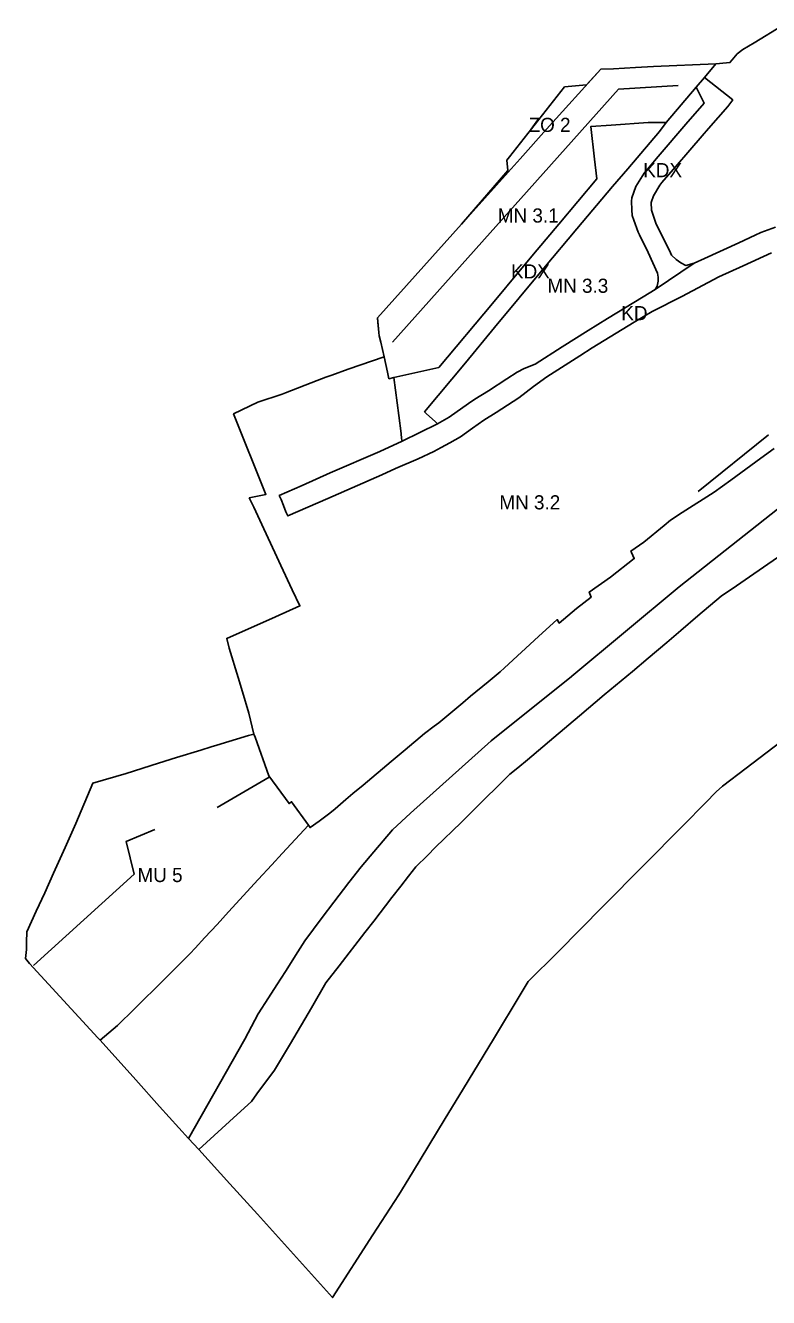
# Model space of a CAD drawing. Extents: x 7421359 to 7422386, y 5546414 to 5547388.
# Drawn here: x 7421565.9 to 7421829.1, y 5546413.6 to 5546863.7 of the extents above; entities that cross this region are included whole.
import ezdxf

# ---------------------------------------------------------------- set-up
doc = ezdxf.new("R2010")
doc.units = 0
for name, color, linetype in [('linie_rozgraniczajace', 7, 'Continuous'), ('linie_zabudowy', 7, 'Continuous'), ('oznaczenia_przeznaczen', 7, 'Continuous')]:
    doc.layers.add(name, color=color, linetype=linetype)

msp = doc.modelspace()

# ---------------------------------------------------------------- linework, layer by layer
at = {"layer": 'linie_rozgraniczajace'}
for points in [[(7421831.57, 5546792.27), (7421826.36, 5546790.44), (7421824.34, 5546789.52), (7421818.56, 5546786.83), (7421806.37, 5546781.19), (7421802.73, 5546779.61), (7421799.77, 5546778.8), (7421798.01, 5546779.74), (7421796.41, 5546780.86), (7421794.76, 5546782.47), (7421794.31, 5546783.28), (7421790.33, 5546791.42), (7421789.31, 5546793.44), (7421787.64, 5546798.3), (7421787.53, 5546801.04), (7421788.33, 5546803.45), (7421790.56, 5546807.24), (7421791.32, 5546808.1), (7421796.08, 5546813.62), (7421801.24, 5546819.59), (7421805.62, 5546824.61), (7421807.86, 5546827.28), (7421814.65, 5546835.07), (7421816.42, 5546837.32), (7421806.38, 5546845.33), (7421810.43, 5546850.09), (7421814.2, 5546850.44), (7421815.41, 5546850.55), (7421815.41, 5546850.55), (7421815.41, 5546850.55), (7421816.19, 5546851.5), (7421818, 5546853.69), (7421819.95, 5546855.16), (7421819.99, 5546855.19), (7421823.97, 5546857.6), (7421834.05, 5546863.7)], [(7421830.11, 5546783.27), (7421820.08, 5546778.69), (7421811.48, 5546774.77), (7421798.35, 5546767.8), (7421787.84, 5546762.51), (7421781.46, 5546758.68), (7421766.61, 5546749.6), (7421762.27, 5546746.83), (7421750.59, 5546739.4), (7421745.84, 5546735.97), (7421740.63, 5546731.91), (7421732.64, 5546726.77), (7421728.26, 5546723.99), (7421724.22, 5546721.19), (7421720.04, 5546718.19), (7421716.23, 5546716.04), (7421713.1, 5546714.3), (7421710.52, 5546712.89), (7421704.95, 5546710.4), (7421697.02, 5546706.9), (7421692.11, 5546704.73), (7421673.06, 5546696.27), (7421658.83, 5546690.12), (7421658.17, 5546691.6), (7421657.3, 5546693.88), (7421656.52, 5546695.93), (7421655.79, 5546697.32), (7421663.88, 5546700.95), (7421673.89, 5546705.39), (7421691.41, 5546712.91), (7421699.3, 5546716.61), (7421711.87, 5546722.75), (7421716.03, 5546725.11), (7421722.82, 5546729.88), (7421725.02, 5546731.44), (7421729.86, 5546734.45), (7421736.41, 5546738.66), (7421740.09, 5546740.97), (7421742.51, 5546742.29), (7421746.38, 5546743.88), (7421755.96, 5546749.97), (7421765.2, 5546755.81), (7421772.07, 5546760.03), (7421784.71, 5546767.67), (7421788.9, 5546770.21), (7421802.73, 5546779.61), (7421806.37, 5546781.19), (7421818.56, 5546786.83), (7421824.34, 5546789.52), (7421826.36, 5546790.44), (7421831.57, 5546792.27)], [(7421699.3, 5546716.61), (7421691.41, 5546712.91), (7421673.89, 5546705.39), (7421663.88, 5546700.95), (7421655.79, 5546697.32), (7421656.52, 5546695.93), (7421657.3, 5546693.88), (7421658.17, 5546691.6), (7421658.83, 5546690.12), (7421673.06, 5546696.27), (7421692.11, 5546704.73), (7421697.02, 5546706.9), (7421704.95, 5546710.4), (7421710.52, 5546712.89), (7421713.1, 5546714.3), (7421716.23, 5546716.04), (7421720.04, 5546718.19), (7421724.22, 5546721.19), (7421728.26, 5546723.99), (7421732.64, 5546726.77), (7421740.63, 5546731.91), (7421745.84, 5546735.97), (7421750.59, 5546739.4), (7421762.27, 5546746.83), (7421766.61, 5546749.6), (7421781.46, 5546758.68), (7421787.84, 5546762.51), (7421798.35, 5546767.8), (7421811.48, 5546774.77), (7421820.08, 5546778.69), (7421830.11, 5546783.27)], [(7421641.26, 5546632.96), (7421638.1, 5546643.34), (7421637.21, 5546646.8), (7421654.48, 5546654.49), (7421663.12, 5546658.33), (7421663.12, 5546658.33), (7421663.12, 5546658.33), (7421660.4, 5546663.99), (7421656.38, 5546672.58), (7421654.95, 5546675.64), (7421649.61, 5546687.07), (7421646.75, 5546693.21), (7421645.2, 5546696.53), (7421645.2, 5546696.53), (7421651.09, 5546697.75), (7421639.62, 5546726.24), (7421648.21, 5546730.34), (7421656.9, 5546733.28), (7421656.9, 5546733.28), (7421658.02, 5546733.72), (7421669.2, 5546738.12), (7421672.36, 5546739.25), (7421674.46, 5546740), (7421680.27, 5546742.07), (7421692.91, 5546746.39), (7421694.15, 5546741.05), (7421694.65, 5546738.7), (7421696.41, 5546739.08), (7421698.12, 5546725.72), (7421698.96, 5546719.29), (7421699.07, 5546717.6), (7421699.3, 5546716.61)], [(7421831.08, 5546714.03), (7421826.4, 5546710.61), (7421815.67, 5546702.79), (7421809.84, 5546698.51), (7421798.46, 5546691.32), (7421794.42, 5546688.6), (7421792.11, 5546686.8), (7421784.96, 5546680.83), (7421780.33, 5546677.68), (7421780.57, 5546677.17), (7421781.55, 5546675.04), (7421773.16, 5546668.47), (7421765.58, 5546663.22), (7421766.32, 5546661.43), (7421761.11, 5546657.36), (7421754.96, 5546652.2), (7421754.24, 5546653.48), (7421747.67, 5546647.49), (7421735.62, 5546636.41), (7421734.06, 5546635.02), (7421729.76, 5546631.46), (7421723.58, 5546626.33), (7421720.85, 5546624.06), (7421715.84, 5546619.89), (7421712.32, 5546616.97), (7421710.61, 5546615.72), (7421707.25, 5546613.2), (7421700.36, 5546607.4), (7421695.39, 5546603.2), (7421685.55, 5546594.93), (7421681.84, 5546591.87), (7421679.35, 5546589.81), (7421675.59, 5546586.52), (7421673.77, 5546584.92), (7421669.93, 5546582.17), (7421666.74, 5546579.89), (7421666.12, 5546580.75), (7421660.2, 5546589.02), (7421659.31, 5546588.37), (7421652.1, 5546598.18), (7421647.26, 5546611.85), (7421646.85, 5546612.88), (7421645.01, 5546620.37), (7421642.8, 5546627.9), (7421641.26, 5546632.96)], [(7421653.13, 5546566.65), (7421656.87, 5546570.72), (7421666.12, 5546580.75), (7421666.74, 5546579.89), (7421669.93, 5546582.17), (7421673.77, 5546584.92), (7421675.59, 5546586.52), (7421679.35, 5546589.81), (7421681.84, 5546591.87), (7421685.55, 5546594.93), (7421695.39, 5546603.2), (7421700.36, 5546607.4), (7421707.25, 5546613.2), (7421710.61, 5546615.72), (7421712.32, 5546616.97), (7421715.84, 5546619.89), (7421720.85, 5546624.06), (7421723.58, 5546626.33), (7421729.76, 5546631.46), (7421734.06, 5546635.02), (7421735.62, 5546636.41), (7421747.67, 5546647.49), (7421754.24, 5546653.48), (7421754.96, 5546652.2), (7421761.11, 5546657.36), (7421766.32, 5546661.43), (7421765.58, 5546663.22), (7421773.16, 5546668.47), (7421781.55, 5546675.04), (7421780.57, 5546677.17), (7421780.33, 5546677.68), (7421784.96, 5546680.83), (7421792.11, 5546686.8), (7421794.42, 5546688.6), (7421798.46, 5546691.32), (7421809.84, 5546698.51), (7421815.67, 5546702.79), (7421826.4, 5546710.61), (7421831.08, 5546714.03)], [(7421836.73, 5546696.13), (7421797.48, 5546665.03), (7421759.42, 5546633.46), (7421759.37, 5546633.43), (7421759.29, 5546633.35), (7421730.86, 5546610.57), (7421702.23, 5546585.01), (7421695.89, 5546579.06), (7421689.36, 5546571.32), (7421684.85, 5546565.99), (7421680.44, 5546560.48), (7421675.18, 5546553.5), (7421671.05, 5546548.05), (7421664.92, 5546539.83), (7421662.44, 5546535.89), (7421657.97, 5546528.89), (7421654.96, 5546524.18), (7421652.02, 5546519.57), (7421648.4, 5546514), (7421643.65, 5546505.05), (7421623.69, 5546469.9), (7421613.38, 5546481.2), (7421605, 5546490.62), (7421592.34, 5546504.65), (7421598.54, 5546509.81), (7421604.57, 5546515.79), (7421615, 5546526.1), (7421618.26, 5546529.33), (7421621.54, 5546532.56), (7421624.24, 5546535.29), (7421626.03, 5546537.24), (7421629.49, 5546540.99), (7421633.77, 5546545.63), (7421637.86, 5546550.09), (7421648.34, 5546561.46), (7421653.13, 5546566.65)], [(7421832.22, 5546675.46), (7421822.39, 5546668.64), (7421817.7, 5546665.44), (7421812.35, 5546661.76), (7421804.06, 5546654.83), (7421798.04, 5546649.65), (7421793.06, 5546645.41), (7421786.47, 5546639.79), (7421780.9, 5546635.14), (7421770.89, 5546626.81), (7421762.09, 5546619.43), (7421753.05, 5546611.72), (7421743.69, 5546603.81), (7421740.28, 5546601.03), (7421737.52, 5546598.73), (7421734.53, 5546595.84), (7421727.25, 5546588.68), (7421720.23, 5546581.68), (7421711.19, 5546572.92), (7421708.3, 5546570.02), (7421704.23, 5546565.95), (7421701.59, 5546562.73), (7421698.84, 5546559.1), (7421695.73, 5546555.07), (7421689.29, 5546546.81), (7421686.08, 5546542.72), (7421676.98, 5546530.97), (7421672.36, 5546524.95), (7421667.2, 5546516.12), (7421659.76, 5546503.46), (7421654.18, 5546494.08), (7421647.91, 5546485.71), (7421645.93, 5546482.9), (7421640.87, 5546478.33), (7421627.28, 5546465.96), (7421623.69, 5546469.9), (7421643.65, 5546505.05), (7421648.4, 5546514), (7421652.02, 5546519.57), (7421654.96, 5546524.18), (7421657.97, 5546528.89), (7421662.44, 5546535.89), (7421664.92, 5546539.83), (7421671.05, 5546548.05), (7421675.18, 5546553.5), (7421680.44, 5546560.48), (7421684.85, 5546565.99), (7421689.36, 5546571.32), (7421695.89, 5546579.06), (7421702.23, 5546585.01), (7421730.86, 5546610.57), (7421759.29, 5546633.35), (7421759.37, 5546633.43), (7421759.42, 5546633.46), (7421797.48, 5546665.03), (7421836.73, 5546696.13)], [(7421708.3, 5546570.02), (7421711.19, 5546572.92), (7421720.23, 5546581.68), (7421727.25, 5546588.68), (7421734.53, 5546595.84), (7421737.52, 5546598.73), (7421740.28, 5546601.03), (7421743.69, 5546603.81), (7421753.05, 5546611.72), (7421762.09, 5546619.43), (7421770.89, 5546626.81), (7421780.9, 5546635.14), (7421786.47, 5546639.79), (7421793.06, 5546645.41), (7421798.04, 5546649.65), (7421804.06, 5546654.83), (7421812.35, 5546661.76), (7421817.7, 5546665.44), (7421822.39, 5546668.64), (7421832.22, 5546675.46)], [(7421838.09, 5546613.77), (7421821.21, 5546600.93), (7421812.78, 5546594.51), (7421810.59, 5546592.51), (7421806.76, 5546588.61), (7421798.86, 5546580.66), (7421770.53, 5546552.04), (7421754.51, 5546535.78), (7421743.97, 5546525.35), (7421741.51, 5546521.32), (7421731.63, 5546505.01), (7421719.4, 5546484.79), (7421714.6, 5546476.97), (7421702.98, 5546457.79), (7421698.12, 5546449.91), (7421688.93, 5546435.71), (7421674.69, 5546413.57), (7421648.06, 5546443.05), (7421638.32, 5546453.86), (7421627.28, 5546465.96), (7421640.87, 5546478.33), (7421645.93, 5546482.9), (7421647.91, 5546485.71), (7421654.18, 5546494.08), (7421659.76, 5546503.46), (7421667.2, 5546516.12), (7421672.36, 5546524.95), (7421676.98, 5546530.97), (7421686.08, 5546542.72), (7421689.29, 5546546.81), (7421695.73, 5546555.07), (7421698.84, 5546559.1), (7421701.59, 5546562.73), (7421704.23, 5546565.95), (7421708.3, 5546570.02)]]:
    msp.add_lwpolyline(points, dxfattribs=at)
for points in [[(7421823.97, 5546857.6), (7421819.99, 5546855.19), (7421819.95, 5546855.16), (7421819.99, 5546855.19)], [(7421818, 5546853.69), (7421816.19, 5546851.5), (7421818, 5546853.69)], [(7421810.43, 5546850.09), (7421806.38, 5546845.33), (7421803.44, 5546841.87), (7421792.81, 5546829.37), (7421786.48, 5546829.41), (7421773.39, 5546828.44), (7421766.1, 5546827.9), (7421767.46, 5546816.41), (7421768.28, 5546809.42), (7421754.87, 5546793.38), (7421747.2, 5546784.25), (7421741.18, 5546777.1), (7421731.29, 5546765.26), (7421712.32, 5546742.65), (7421696.41, 5546739.08), (7421694.65, 5546738.7), (7421694.15, 5546741.05), (7421692.91, 5546746.39), (7421692.91, 5546746.39), (7421691.74, 5546751.58), (7421691.23, 5546753.84), (7421691.02, 5546755.05), (7421690.66, 5546760.21), (7421720.39, 5546793.42), (7421720.39, 5546793.42), (7421736.91, 5546811.78), (7421741.17, 5546816.51), (7421750.49, 5546826.95), (7421769.64, 5546848.17), (7421774.14, 5546848.4), (7421781.95, 5546848.84), (7421788.3, 5546849.19), (7421810.4, 5546850.09)], [(7421781.95, 5546848.84), (7421774.14, 5546848.4), (7421769.64, 5546848.17), (7421769.64, 5546848.17), (7421774.14, 5546848.4)], [(7421815.41, 5546850.55), (7421815.41, 5546850.55), (7421814.2, 5546850.44)], [(7421769.64, 5546848.17), (7421750.49, 5546826.95), (7421741.17, 5546816.51), (7421736.91, 5546811.78), (7421720.39, 5546793.42), (7421736.78, 5546812.38), (7421736.42, 5546815.98), (7421737.37, 5546817.19), (7421756.88, 5546841.97), (7421764.67, 5546842.66)], [(7421806.38, 5546845.33), (7421816.42, 5546837.32), (7421814.65, 5546835.07), (7421807.86, 5546827.28), (7421805.62, 5546824.61), (7421801.24, 5546819.59), (7421796.08, 5546813.62), (7421791.32, 5546808.1), (7421790.56, 5546807.24), (7421788.33, 5546803.45), (7421787.53, 5546801.04), (7421787.64, 5546798.3), (7421789.31, 5546793.44), (7421790.33, 5546791.42), (7421794.31, 5546783.28), (7421794.76, 5546782.47), (7421796.41, 5546780.86), (7421798.01, 5546779.74), (7421799.77, 5546778.8), (7421802.73, 5546779.61), (7421788.9, 5546770.21), (7421789.59, 5546771.49), (7421790.02, 5546773.21), (7421790.01, 5546774.65), (7421789.8, 5546776.03), (7421786.4, 5546783.4), (7421783.43, 5546789.55), (7421782.91, 5546790.56), (7421781.43, 5546794.75), (7421780.81, 5546796.44), (7421780.63, 5546798.49), (7421780.5, 5546801.55), (7421780.69, 5546802.75), (7421782.04, 5546806.69), (7421785, 5546811.46), (7421790.01, 5546817.3), (7421799.85, 5546828.71), (7421806.24, 5546836.15), (7421803.44, 5546841.87)], [(7421803.44, 5546841.87), (7421806.24, 5546836.15), (7421799.85, 5546828.71), (7421790.01, 5546817.3), (7421785, 5546811.46), (7421782.04, 5546806.69), (7421780.69, 5546802.75), (7421780.5, 5546801.55), (7421780.63, 5546798.49), (7421780.81, 5546796.44), (7421781.43, 5546794.75), (7421782.91, 5546790.56), (7421783.43, 5546789.55), (7421786.4, 5546783.4), (7421789.8, 5546776.03), (7421790.01, 5546774.65), (7421790.02, 5546773.21), (7421789.59, 5546771.49), (7421788.9, 5546770.21), (7421784.71, 5546767.67), (7421772.07, 5546760.03), (7421765.2, 5546755.81), (7421755.96, 5546749.97), (7421746.38, 5546743.88), (7421742.51, 5546742.29), (7421740.09, 5546740.97), (7421736.41, 5546738.66), (7421729.86, 5546734.45), (7421725.02, 5546731.44), (7421722.82, 5546729.88), (7421716.03, 5546725.11), (7421711.87, 5546722.75), (7421711.1, 5546723.48), (7421707.89, 5546726.4), (7421707.26, 5546727.01), (7421721.71, 5546744.37), (7421732.05, 5546756.83), (7421749.49, 5546777.79), (7421761.2, 5546791.73), (7421773.82, 5546806.66), (7421779.28, 5546812.96), (7421787.11, 5546822.23), (7421790.42, 5546826.16), (7421792.8, 5546829.36), (7421792.81, 5546829.37)], [(7421696.41, 5546739.08), (7421712.32, 5546742.65), (7421731.29, 5546765.26), (7421741.18, 5546777.1), (7421747.2, 5546784.25), (7421754.87, 5546793.38), (7421768.28, 5546809.42), (7421767.46, 5546816.41), (7421766.1, 5546827.9), (7421773.39, 5546828.44), (7421786.48, 5546829.41), (7421792.81, 5546829.37), (7421792.8, 5546829.36), (7421790.42, 5546826.16), (7421787.11, 5546822.23), (7421779.28, 5546812.96), (7421773.82, 5546806.66), (7421761.2, 5546791.73), (7421749.49, 5546777.79), (7421732.05, 5546756.83), (7421721.71, 5546744.37), (7421707.26, 5546727.01), (7421707.89, 5546726.4), (7421711.1, 5546723.48), (7421711.87, 5546722.75), (7421699.3, 5546716.61), (7421699.07, 5546717.6), (7421698.96, 5546719.29), (7421698.12, 5546725.72)], [(7421720.39, 5546793.42), (7421690.66, 5546760.21), (7421690.66, 5546760.21)], [(7421690.66, 5546760.21), (7421690.66, 5546760.21), (7421691.02, 5546755.05), (7421691.23, 5546753.84), (7421691.02, 5546755.05), (7421690.76, 5546758.75), (7421690.66, 5546760.21)], [(7421639.63, 5546726.25), (7421639.62, 5546726.24), (7421639.62, 5546726.24)], [(7421656.38, 5546672.58), (7421660.4, 5546663.99), (7421663.12, 5546658.33), (7421663.12, 5546658.33), (7421660.4, 5546663.99)], [(7421646.85, 5546612.88), (7421647.26, 5546611.85), (7421652.1, 5546598.18), (7421659.31, 5546588.37), (7421660.2, 5546589.02), (7421666.12, 5546580.75), (7421656.87, 5546570.72), (7421653.13, 5546566.65), (7421648.34, 5546561.46), (7421637.86, 5546550.09), (7421633.77, 5546545.63), (7421629.49, 5546540.99), (7421626.03, 5546537.24), (7421624.24, 5546535.29), (7421621.54, 5546532.56), (7421618.26, 5546529.33), (7421615, 5546526.1), (7421604.57, 5546515.79), (7421598.54, 5546509.81), (7421592.34, 5546504.65), (7421591.6, 5546505.48), (7421588.81, 5546508.41), (7421567.42, 5546531.8), (7421565.92, 5546533.59), (7421566.32, 5546536.78), (7421566.35, 5546539.3), (7421566.39, 5546542.93), (7421569.74, 5546550.32), (7421572.76, 5546556.8), (7421575.89, 5546563.74), (7421579.95, 5546572.77), (7421582.33, 5546578.07), (7421583.79, 5546581.34), (7421589.75, 5546595.58), (7421601.55, 5546599.06), (7421613.02, 5546602.65), (7421619.43, 5546604.66), (7421628.03, 5546607.29), (7421631.7, 5546608.42), (7421633.72, 5546609.04), (7421644.96, 5546612.48), (7421646.85, 5546612.88)], [(7421582.33, 5546578.07), (7421579.95, 5546572.77), (7421575.89, 5546563.74), (7421579.95, 5546572.77)], [(7421566.35, 5546539.3), (7421566.32, 5546536.78), (7421565.92, 5546533.59), (7421566.32, 5546536.78)]]:
    msp.add_lwpolyline(points, close=True, dxfattribs=at)
at = {"layer": 'linie_zabudowy'}
for points in [[(7421695.9, 5546751.59), (7421775.9, 5546841.1), (7421797.08, 5546842.4)], [(7421804.2, 5546698.81), (7421829.07, 5546718.88)], [(7421633.78, 5546587.03), (7421652.28, 5546597.71)], [(7421568.74, 5546531.12), (7421604.48, 5546563.42), (7421601.56, 5546574.92), (7421611.71, 5546579.21)]]:
    msp.add_lwpolyline(points, dxfattribs=at)

# ---------------------------------------------------------------- texts
at = {"layer": 'oznaczenia_przeznaczen'}
for s, p in [('ZO 2', (7421744.098791, 5546826.020011)), ('KDX', (7421784.701517, 5546810.001229)), ('MN 3.1', (7421733.191371, 5546793.950011)), ('KDX', (7421737.875988, 5546774.160011)), ('MN 3.3', (7421750.769385, 5546769.090011)), ('KD', (7421776.929663, 5546759.398276)), ('MN 3.2', (7421733.755581, 5546692.460011)), ('MU 5', (7421605.607875, 5546560.580011))]:
    msp.add_text(s, height=4.999998, dxfattribs=at).set_placement(p)

doc.saveas('drawing.dxf')
